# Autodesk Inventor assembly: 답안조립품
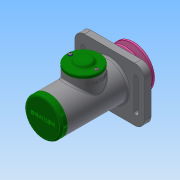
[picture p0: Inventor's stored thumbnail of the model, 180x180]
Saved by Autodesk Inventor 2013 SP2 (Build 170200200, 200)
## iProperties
Created: 2021-07
Part Number: 답안조립품
Document SubType Name: Assembly
Designer: kumcom2
Author: kumcom2
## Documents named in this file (20)
- C:\Users\kumcom2\Desktop\710706V1030\답안조립품.iam
- C:\Users\kumcom2\Desktop\710706V1030\본체.ipt
- C:\Users\kumcom2\Desktop\710706V1030\V-벨트풀리.ipt
- C:\Users\kumcom2\Desktop\710706V1030\너트 M10.ipt
- C:\Users\kumcom2\Desktop\710706V1030\멈춤링 15 x 1.ipt
- C:\Users\kumcom2\Desktop\710706V1030\멈춤링 35 x 1.6.ipt
- C:\Users\kumcom2\Desktop\710706V1030\베어링 15 x 35 x 11.ipt
- C:\Users\kumcom2\Desktop\710706V1030\볼트 M4 x 10.ipt
- C:\Users\kumcom2\Desktop\710706V1030\부시1.ipt
- C:\Users\kumcom2\Desktop\710706V1030\부시2.ipt
- C:\Users\kumcom2\Desktop\710706V1030\사이드 커버.ipt
- 사이드 커버.ipt
- C:\Users\kumcom2\Desktop\710706V1030\십자볼트 M3 x 10.ipt
- C:\Users\kumcom2\Desktop\710706V1030\오일 실 15 25 7.ipt
- C:\Users\kumcom2\Desktop\710706V1030\와셔 3 x 6.ipt
- C:\Users\kumcom2\Desktop\710706V1030\와셔 4 x 16.ipt
- C:\Users\kumcom2\Desktop\710706V1030\와셔 10 x 21.ipt
- C:\Users\kumcom2\Desktop\710706V1030\축.ipt
- C:\Users\kumcom2\Desktop\710706V1030\키 4 x 4 x 18.ipt
- C:\Users\kumcom2\Desktop\710706V1030\탑 커버.ipt
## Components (2 placed, 2 different names)
1. V-벨트풀리:1 — 각도:2
2. ISO 4017 M4 x 10:1
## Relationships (1: Angle 1)
- 각도:2 [Angle]: V-벨트풀리:1
